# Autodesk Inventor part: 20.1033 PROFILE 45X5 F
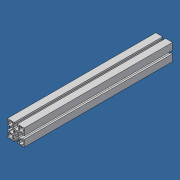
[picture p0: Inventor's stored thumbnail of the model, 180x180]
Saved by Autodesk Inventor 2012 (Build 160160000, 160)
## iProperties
Created: 2011-09
Part Number: 20.1033 PROFILE 45X5 F
Material: Aluminum-6061
Description: L = TRAVEL + 3.74", T1E M8
Document SubType Name: Modeling
Designer: Administrator
Density: 2.71 g/cm^3
Vendor: F
FINISH: CLEAR ANODIZED
Author: Administrator
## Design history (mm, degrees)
sketch "Sketch1"
  geometry: L1 (-4.1, -22.5)-(-4.1, -18) reference; L2 (-4.6, -18)-(-6.8, -18) reference; L3 (-6.8, -18)-(-6.8, -9.5) reference; L4 (-6.8, -9.5)-(-4.5, -7.2) reference; L5 (-4.5, -7.2)-(4.5, -7.2) reference; L6 (4.5, -7.2)-(6.8, -9.5) reference; L7 (6.8, -9.5)-(6.8, -18) reference; L8 (4.1, -18)-(4.1, -22.5) reference; L9 (22.5, -4.1)-(18, -4.1) reference; L10 (18, -4.6)-(18, -6.8) reference; L11 (18, -6.8)-(9.5, -6.8) reference; L12 (9.5, -6.8)-(7.2, -4.5) reference; L13 (7.2, -4.5)-(7.2, 4.5) reference; L14 (7.2, 4.5)-(9.5, 6.8) reference; L15 (9.5, 6.8)-(18, 6.8) reference; L16 (18, 4.1)-(22.5, 4.1) reference; L17 (22.5, 22.5)-(22.5, 4.4) reference; L18 (4.1, 22.5)-(4.1, 18) reference; L19 (4.6, 18)-(6.8, 18) reference; L20 (6.8, 18)-(6.8, 9.5) reference; L21 (6.8, 9.5)-(4.5, 7.2) reference; L22 (4.5, 7.2)-(-4.5, 7.2) reference; L23 (-4.5, 7.2)-(-6.8, 9.5) reference; L24 (-6.8, 9.5)-(-6.8, 18) reference; L25 (-4.1, 18)-(-4.1, 22.5) reference; L26 (-22.5, 22.5)-(-4.4, 22.5) reference; L27 (-22.5, 4.1)-(-18, 4.1) reference; L28 (-18, 6.8)-(-9.5, 6.8) reference; L29 (-9.5, 6.8)-(-7.2, 4.5) reference; L30 (-7.2, 4.5)-(-7.2, -4.5) reference; L31 (-7.2, -4.5)-(-9.5, -6.8) reference; L32 (-9.5, -6.8)-(-18, -6.8) reference; L33 (-18, -6.8)-(-18, -4.6) reference; L34 (-18, -4.1)-(-22.5, -4.1) reference; L35 (-22.5, -22.5)-(-22.5, -4.4) reference; L36 (-4.4, -22.5)-(-22.5, -22.5) reference; L37 (-4.596, -3.182)-(-3.263, -1.849) reference; L38 (-3.263, 1.849)-(-4.596, 3.182) reference; L39 (-4.596, 3.182)-(-3.182, 4.596) reference; L40 (-3.182, 4.596)-(-1.849, 3.263) reference; L41 (1.849, 3.263)-(3.182, 4.596) reference; L42 (3.182, 4.596)-(4.596, 3.182) reference; L43 (4.596, 3.182)-(3.263, 1.849) reference; L44 (3.263, -1.849)-(4.596, -3.182) reference; L45 (4.596, -3.182)-(3.182, -4.596) reference; L46 (3.182, -4.596)-(1.849, -3.263) reference; L47 (-1.849, -3.263)-(-3.182, -4.596) reference; L48 (-3.182, -4.596)-(-4.596, -3.182) reference; L49 (13.8, -8.8)-(20.5, -8.8) reference; L50 (20.5, -8.8)-(20.5, -15.5) reference; L51 (15.5, -20.5)-(8.8, -20.5) reference; L52 (8.8, -20.5)-(8.8, -13.8) reference; L53 (8.8, 13.8)-(8.8, 20.5) reference; L54 (8.8, 20.5)-(15.5, 20.5) reference; L55 (20.5, 15.5)-(20.5, 8.8) reference; L56 (20.5, 8.8)-(13.8, 8.8) reference; L57 (-13.8, 8.8)-(-20.5, 8.8) reference; L58 (-20.5, 8.8)-(-20.5, 15.5) reference; L59 (-15.5, 20.5)-(-8.8, 20.5) reference; L60 (-8.8, 20.5)-(-8.8, 13.8) reference; L61 (-8.8, -13.8)-(-8.8, -20.5) reference; L62 (-8.8, -20.5)-(-15.5, -20.5) reference; L63 (-20.5, -15.5)-(-20.5, -8.8) reference; L64 (-20.5, -8.8)-(-13.8, -8.8) reference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; A1 r 3.75 centre (0, 0) between (3.362, -1.66) and (3.362, 1.66) reference; A2 r 5 centre (13.8, -13.8) between (13.8, -8.8) and (8.8, -13.8) reference; A3 r 5 centre (15.5, -15.5) between (15.5, -20.5) and (20.5, -15.5) reference; A4 r 5 centre (13.8, 13.8) between (8.8, 13.8) and (13.8, 8.8) reference; A5 r 5 centre (15.5, 15.5) between (20.5, 15.5) and (15.5, 20.5) reference; A6 r 5 centre (-13.8, 13.8) between (-13.8, 8.8) and (-8.8, 13.8) reference; A7 r 5 centre (-15.5, 15.5) between (-15.5, 20.5) and (-20.5, 15.5) reference; A8 r 5 centre (-13.8, -13.8) between (-8.8, -13.8) and (-13.8, -8.8) reference; A9 r 5 centre (-15.5, -15.5) between (-20.5, -15.5) and (-15.5, -20.5) reference; A10 r 3.75 centre (0, 0) between (3.362, 1.66) and (3.263, 1.849) reference; A11 r 3.75 centre (0, 0) between (1.849, 3.263) and (-1.66, 3.362) reference; A12 r 3.75 centre (0, 0) between (-1.66, 3.362) and (-1.849, 3.263) reference; A13 r 3.75 centre (0, 0) between (-3.263, 1.849) and (-3.263, -1.849) reference; A14 r 3.75 centre (0, 0) between (-1.849, -3.263) and (-1.66, -3.362) reference; A15 r 3.75 centre (0, 0) between (-1.66, -3.362) and (1.849, -3.263) reference; A16 r 3.75 centre (0, 0) between (3.263, -1.849) and (3.362, -1.66) reference
  constraints: 160 end point, 32 point on circle, 30 horizontal, 30 vertical, 16 centre point, 144 other
extrude "Extrusion1" new body sketch "Sketch1" distance "d0" = 399.8; taper "d1" = 0 deg
thread "Thread1" dims "d2" = 25.4, "d3" = 0
thread "Thread2" dims "d4" = 25.4, "d5" = 0
thread "Thread3" dims "d6" = 25.4, "d7" = 0
thread "Thread4" dims "d8" = 25.4, "d9" = 0
body "Solid1"
